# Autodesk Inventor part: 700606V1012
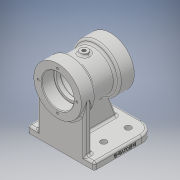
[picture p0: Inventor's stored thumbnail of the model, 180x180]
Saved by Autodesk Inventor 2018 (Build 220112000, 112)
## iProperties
Created: 2020-06
Part Number: 700606V1012
Material: 일반
Document SubType Name: Modeling
Designer: USER
Density: 1 g/cm^3
Appearance: 기본값
Author: USER
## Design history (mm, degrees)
sketch "스케치1"
  geometry: L1 (-45, -49)-(45, -49); L2 (45, -49)-(45, 49); L3 (45, 49)-(-45, 49); L4 (-45, 49)-(-45, -49); L5 (-45, -49)-(45, 49); L6 (45, -49)-(-45, 49); 1 further point
  constraints: 12 end point, 2 midpoint, 2 parallel, 1 horizontal, 1 perpendicular
  dimensions: "d0" = 90 distance of L2.end L3.end; "d1" = 98 distance of L1.end L2.end
extrude "돌출1" new body sketch "스케치1" distance "d2" = 10; taper "d3" = 0 deg
sketch "스케치2"
  geometry: L1 (61.759, 80)-(-72.419, 80); L2 (-45, 0)-(45, 0) reference; L3 (50, 109)-(-28, 109); L4 (-28, 109)-(-28, 103.5); L5 (-28, 103.5)-(-10, 103.5); L6 (-10, 103.5)-(-10, 100); L7 (-10, 100)-(-4, 100); L8 (-4, 100)-(-4, 100); L9 (-1, 103)-(23, 103); L10 (26, 100)-(26, 100); L11 (26, 100)-(32, 100); L12 (32, 100)-(32, 103.5); L13 (32, 103.5)-(50, 103.5); L14 (50, 103.5)-(50, 109); L15 (45, 0)-(45, 10) reference; A1 r 3 centre (23, 100) between (26, 100) and (23, 103); A2 r 3 centre (-1, 100) between (-1, 103) and (-4, 100); 3 further points
  constraints: 26 end point, 11 perpendicular, 4 point on circle, 4 point on line, 4 tangent, 2 centre point, 2 horizontal, 1 equal radius
  dimensions: "d4" = 80 distance between parallel lines of L2 L1; "d5" = 58 diameter of L3 L1; "d6" = 47 diameter of L13 L1; "d7" = 40 diameter of L11 L1; "d8" = 46 diameter of L9 L1; "d9" = 40 diameter of L7 L1; "d10" = 47 diameter of L5 L1; "d11" = 78 distance between parallel lines of L4 L14; "d12" = 5 distance between parallel lines of L15 L14; "d13" = 18 distance between parallel lines of L12 L14; "d14" = 6 distance of L10.end L11.end; "d15" = 30 distance of point (-4, 103) point (26, 103); "d16" = 18 distance of L4.end L5.end; "d17" = 3 radius of A1
revolve "회전1" sketch "스케치2" stored, may be unused: angle "d18" = 90 deg
sketch "스케치4"
  geometry: C1 r 20 at (0, 0) reference; C2 r 23.5 at (0, 0) reference; C3 r 35 at (0, 0); 1 further point
  constraints: 1 centre point, 1 coincident
  dimensions: "d22" = 70 diameter of C3
extrude "돌출3" join sketch "스케치4" distance "d23" = 22; taper "d24" = 0 deg
sketch "스케치5"
  geometry: L1 (-45, 49)-(-45, -49) reference; L2 (-45, 35)-(-35, 35); L3 (-35, 35)-(-35, -35); L4 (-35, -35)-(-45, -35); L5 (-45, -35)-(-45, 35); 2 further points
  constraints: 8 end point, 2 parallel, 1 horizontal, 1 horizontal alignment, 1 midpoint, 1 perpendicular, 1 point on line
  dimensions: "d25" = 10 distance of L2.start L2.end; "d26" = 70 distance of L2.end L3.end
sketch "스케치6"
  geometry: L1 (-45, 10)-(45, 10) reference; L2 (-33, 10)-(-26.019, 29.179); L3 (-45, 0)-(-45, 10) reference; 1 further point
  constraints: 2 end point, 1 point on line
  dimensions: "d29" = 70 deg angle of L1 L2; "d30" = 12 distance from line of L3 L2.start
sketch "스케치8" dims "d48" = 57
  geometry: C1 r 20 at (0, 0) reference; 3 further points
  constraints: 2 vertical alignment, 1 coincident, 2 other
hole "구멍2" sketch "스케치8" at (0, 28.5) diameter "d49" = 3.242; stored, may be unused: countersink angle "d53" = 90 deg, drill point angle "d55" = 118 deg; dims "d50" = 10, "d51" = 4, "d52" = 2, "d54" = 12
sketch "스케치10"
  geometry: L1 (-45, 49)-(-45, -49) reference; C1 r 4.5 at (-11, 29); C2 r 4.5 at (25, 29); 1 further point
  constraints: 2 centre point, 1 horizontal alignment
  dimensions: "d70" = 9 diameter of C1; "d71" = 9 diameter of C2; "d72" = 36 distance of C2.centre C1.centre; "d73" = 70 distance from line of L1 C2.centre; "d74" = 29 vertical distance of point (0, 0) C2.centre
extrude "돌출5" cut sketch "스케치10" extent not by distance; stored distance "d75" = 22; taper "d76" = 0 deg
node "작업 평면1"
sketch "스케치11"
  geometry: L1 (-45, 0)-(45, 0) reference; L2 (-45, 0)-(-45, 10) reference; 2 further points
  constraints: 1 other
  dimensions: "d78" = 4 distance from line of L1 point (0, 4); "d79" = 45 distance from line of L2 point (0, 4)
feature "엠보싱1" sketch "스케치11" dims "d0" = 90, "d1" = 98, "d5" = 58, "d80" = 0.5, "d81" = 0
node "작업 평면2"
sketch "스케치12"
  geometry: L1 (-50, -35)-(-50, 35) reference; C1 r 6 at (-11, 0); 1 further point
  constraints: 1 centre point, 1 horizontal alignment
  dimensions: "d83" = 12 diameter of C1; "d84" = 39 distance from line of L1 C1.centre
extrude "돌출6" join sketch "스케치12" stored distance "d85" = 22; taper "d86" = 0 deg
hole "구멍4" diameter "d89" = 5.188; stored, may be unused: countersink angle "d93" = 90 deg, drill point angle "d95" = 118 deg; dims "d87" = 10, "d88" = 10, "d90" = 30, "d91" = 4, "d92" = 2, "d94" = 30
chamfer "모따기1" distance "d96" = 1; stored, may be unused: second distance "d97" = 2, angle "d98" = 45 deg
fillet "모깎기1" dims "d99" = 3
fillet "모깎기4" dims "d102" = 20
sketch "스케치13"
  geometry: C1 r 20 at (0, 0) reference; C2 r 35 at (0, 0); C3 r 29 at (0, 0); 1 further point
  constraints: 2 centre point, 2 coincident
  dimensions: "d106" = 70 diameter of C2; "d107" = 58 diameter of C3
extrude "돌출7" join sketch "스케치13" distance "d108" = 22; taper "d109" = 0 deg
extrude "돌출8" join sketch "스케치5" stored distance "d110" = 22; taper "d111" = 0 deg
feature "리브2" dims "d112" = 1, "d113" = 10, "d114" = 0, "d115" = 0, "d116" = 1, "d117" = 1
sketch "스케치14" dims "d118" = 57
  geometry: C1 r 20 at (0, 0) reference; 3 further points
  constraints: 2 horizontal alignment, 1 coincident, 2 other
hole "구멍5" sketch "스케치14" at (28.5, 0) diameter "d119" = 3.242; stored, may be unused: countersink angle "d123" = 90 deg, drill point angle "d125" = 118 deg; dims "d120" = 10, "d121" = 4, "d122" = 2, "d124" = 12
chamfer "모따기2" distance "d129" = 1; stored, may be unused: second distance "d130" = 2, angle "d131" = 45 deg
fillet "모깎기8" dims "d132" = 3
fillet "모깎기9" dims "d133" = 3
fillet "모깎기10" dims "d134" = 3
fillet "모깎기11" dims "d135" = 0.3
fillet "모깎기12" dims "d136" = 3
node "솔리드1"
pattern_circular "원형 패턴2" dims angle "d57" = 360 deg
mirror "미러1"
pattern_circular "원형 패턴4" dims angle "d127" = 360 deg
node "투영된 루프1"
other parameters: "d77" = -71.75, "d82" = 112
